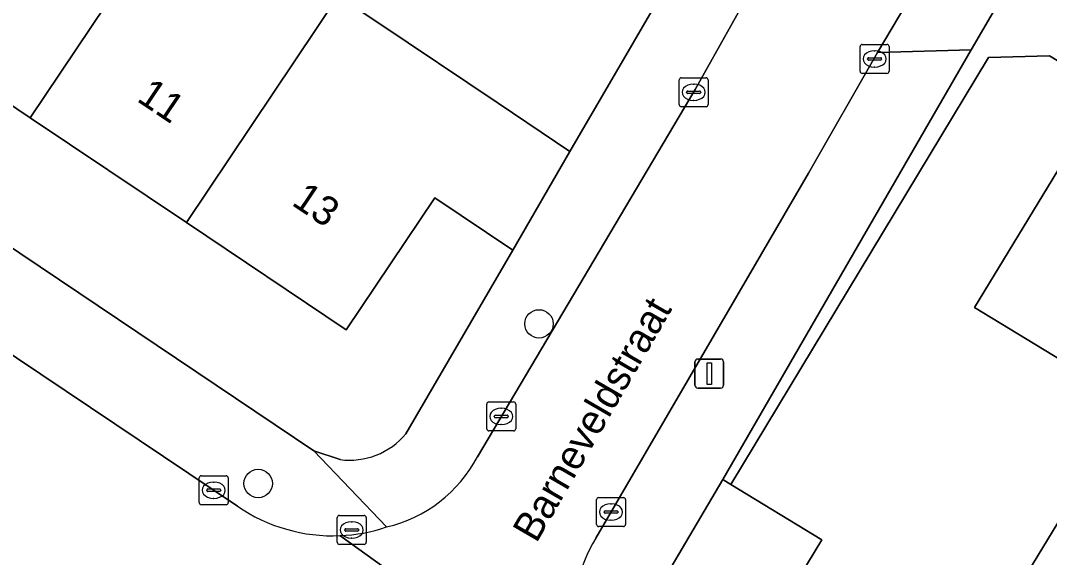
# Model space of a CAD drawing. Extents: x 158352 to 159489, y 383828 to 384603.
# Drawn here: x 158789.93 to 158825.42, y 383963.32 to 383981.83 of the extents above; entities that cross this region are included whole.
import ezdxf

# ---------------------------------------------------------------- set-up
doc = ezdxf.new("R2010")
doc.units = 0
for name, color, linetype in [('IMGEO_Boom', 7, 'Continuous'), ('IMGEO_Brandkraan', 7, 'Continuous'), ('IMGEO_Erf', 7, 'Continuous'), ('IMGEO_Kolk', 7, 'Continuous'), ('IMGEO_Lichtmast', 7, 'Continuous'), ('IMGEO_Openbare_ruimte_label', 7, 'Continuous'), ('IMGEO_Pand', 7, 'Continuous'), ('IMGEO_Pand_nummerreeks', 7, 'Continuous'), ('IMGEO_Rijbaan_lokaal_open', 7, 'Continuous'), ('IMGEO_Voetpad_open', 7, 'Continuous')]:
    doc.layers.add(name, color=color, linetype=linetype)

msp = doc.modelspace()

# ---------------------------------------------------------------- linework, layer by layer
at = {"layer": 'IMGEO_Boom'}
for centre in [(158807.812, 383971.377), (158798.125, 383965.871)]:
    msp.add_circle(centre, 0.489, dxfattribs=at)
at = {"layer": 'IMGEO_Brandkraan'}
for p, q in [((158800.851, 383963.843), (158800.851, 383964.695)), ((158800.926, 383964.769), (158801.778, 383964.769)), ((158801.339, 383964.549), (158801.364, 383964.549)), ((158801.852, 383964.695), (158801.852, 383963.843)), ((158801.11, 383964.263), (158801.11, 383964.275)), ((158801.548, 383964.226), (158801.15, 383964.226)), ((158801.153, 383964.312), (158801.551, 383964.312)), ((158801.594, 383964.275), (158801.594, 383964.263)), ((158801.362, 383963.989), (158801.337, 383963.989)), ((158801.778, 383963.769), (158800.926, 383963.769))]:
    msp.add_line(p, q, dxfattribs=at)
for points in [[(158800.851, 383963.843), (158800.851, 383964.695)], [(158800.926, 383964.769), (158801.778, 383964.769)], [(158801.852, 383964.695), (158801.852, 383963.843)], [(158801.778, 383963.769), (158800.926, 383963.769)]]:
    msp.add_lwpolyline(points, dxfattribs=at)
for centre, radius, start, end in [((158800.928, 383964.693), 0.0765, 91.552, 178.448), ((158800.928, 383964.693), 0.0765, 91.552, 178.448), ((158801.776, 383964.693), 0.0765, 1.552, 88.448), ((158801.776, 383964.693), 0.0765, 1.552, 88.448), ((158801.15, 383964.272), 0.0403, 85.8775, 175.7526), ((158801.147, 383964.262), 0.0366, 178.938, 274.7102), ((158801.551, 383964.269), 0.043, 264.8664, 352.4533), ((158801.555, 383964.274), 0.0386, 1.7309, 96.639), ((158800.928, 383963.845), 0.0765, 181.552, 268.448), ((158800.928, 383963.845), 0.0765, 181.552, 268.448), ((158801.776, 383963.845), 0.0765, 271.552, 358.448), ((158801.776, 383963.845), 0.0765, 271.552, 358.448)]:
    msp.add_arc(centre, radius, start, end, dxfattribs=at)
for centre, major_axis, ratio, start_param, end_param in [((158801.338, 383964.269), (-0.387, 0.002), 0.722429, 4.712389, 7.853982), ((158801.363, 383964.269), (-0.39, 0.002), 0.717154, 1.570796, 4.712389)]:
    msp.add_ellipse(centre, major_axis=major_axis, ratio=ratio, start_param=start_param, end_param=end_param, dxfattribs=at)
at = {"layer": 'IMGEO_Erf'}
for points in [[(158802.097, 384002.012), (158799.476, 383998.101), (158797.684, 383995.427), (158795.003, 383997.224), (158790.103, 383989.919), (158795.501, 383986.297), (158800.89, 383982.683), (158802.252, 383981.769), (158806.404, 383978.983), (158808.882, 383977.32), (158813.315, 383984.944), (158808.396, 383988.244), (158805.207, 383983.49), (158802.603, 383985.237), (158805.792, 383989.991), (158803.033, 383991.842), (158804.825, 383994.513), (158807.584, 383992.662), (158810.663, 383997.498), (158810.838, 383997.754), (158812.948, 383995.246), (158812.308, 383998.709), (158812.069, 384000)], [(158795.651, 383974.873), (158790.263, 383978.487), (158784.865, 383982.109), (158779.474, 383985.725), (158774.102, 383989.328), (158768.703, 383992.949), (158763.122, 383996.693), (158760.865, 383993.334), (158800.049, 383966.997), (158800.949, 383966.697)], [(158849.616, 383965.92), (158846.84, 383967.608), (158845.169, 383964.859), (158842.366, 383966.562), (158839.602, 383968.242), (158841.273, 383970.991), (158835.6, 383974.441), (158833.929, 383971.692), (158831.114, 383973.403), (158828.362, 383975.075), (158830.033, 383977.824), (158827.393, 383979.426), (158822.843, 383971.94), (158828.233, 383968.664), (158826.585, 383965.952), (158832.219, 383962.527), (158837.825, 383959.119), (158843.416, 383955.721), (158848.864, 383952.409)], [(158803.223, 383967.587), (158806.907, 383973.916), (158804.217, 383975.722), (158801.166, 383971.174), (158795.651, 383974.873)], [(158849.585, 383940.963), (158843.929, 383944.401), (158838.53, 383947.683), (158832.926, 383951.089), (158827.264, 383954.531), (158821.699, 383957.914), (158816.018, 383961.367), (158817.576, 383963.931), (158814.431, 383965.842), (158814.158, 383966.008), (158811.467, 383961.443)]]:
    msp.add_lwpolyline(points, dxfattribs=at)
msp.add_arc((158801.279, 383969.204), 2.529, 262.504, 320.2449, dxfattribs=at)
at = {"layer": 'IMGEO_Kolk'}
for p, q in [((158818.893, 383980.087), (158818.893, 383980.939)), ((158818.968, 383981.013), (158819.82, 383981.013)), ((158819.894, 383980.939), (158819.894, 383980.087)), ((158819.152, 383980.507), (158819.152, 383980.519)), ((158819.195, 383980.556), (158819.593, 383980.556)), ((158819.381, 383980.793), (158819.406, 383980.793)), ((158819.636, 383980.519), (158819.636, 383980.507)), ((158819.59, 383980.47), (158819.192, 383980.47)), ((158819.404, 383980.233), (158819.379, 383980.233)), ((158812.649, 383978.937), (158812.649, 383979.789)), ((158812.724, 383979.863), (158813.576, 383979.863)), ((158813.65, 383979.789), (158813.65, 383978.937)), ((158819.82, 383980.013), (158818.968, 383980.013)), ((158813.137, 383979.643), (158813.162, 383979.643)), ((158812.908, 383979.357), (158812.908, 383979.369)), ((158813.346, 383979.32), (158812.948, 383979.32)), ((158812.951, 383979.406), (158813.349, 383979.406)), ((158813.16, 383979.083), (158813.135, 383979.083)), ((158813.392, 383979.369), (158813.392, 383979.357)), ((158813.576, 383978.863), (158812.724, 383978.863)), ((158806.012, 383967.758), (158806.012, 383968.61)), ((158806.087, 383968.684), (158806.939, 383968.684)), ((158806.5, 383968.464), (158806.525, 383968.464)), ((158807.013, 383968.61), (158807.013, 383967.758)), ((158806.271, 383968.178), (158806.271, 383968.19)), ((158806.709, 383968.141), (158806.311, 383968.141)), ((158806.314, 383968.227), (158806.712, 383968.227)), ((158806.755, 383968.19), (158806.755, 383968.178)), ((158806.523, 383967.904), (158806.498, 383967.904)), ((158806.939, 383967.684), (158806.087, 383967.684)), ((158796.09, 383965.213), (158796.09, 383966.065)), ((158796.165, 383966.139), (158797.017, 383966.139)), ((158797.091, 383966.065), (158797.091, 383965.213)), ((158796.349, 383965.633), (158796.349, 383965.645)), ((158796.787, 383965.596), (158796.389, 383965.596)), ((158796.392, 383965.682), (158796.79, 383965.682)), ((158796.578, 383965.919), (158796.603, 383965.919)), ((158796.833, 383965.645), (158796.833, 383965.633)), ((158796.601, 383965.359), (158796.576, 383965.359)), ((158809.798, 383964.462), (158809.798, 383965.314)), ((158809.873, 383965.388), (158810.725, 383965.388)), ((158810.799, 383965.314), (158810.799, 383964.462)), ((158797.017, 383965.139), (158796.165, 383965.139)), ((158810.057, 383964.882), (158810.057, 383964.894)), ((158810.1, 383964.931), (158810.498, 383964.931)), ((158810.286, 383965.168), (158810.311, 383965.168)), ((158810.541, 383964.894), (158810.541, 383964.882)), ((158810.495, 383964.845), (158810.097, 383964.845)), ((158810.309, 383964.608), (158810.284, 383964.608)), ((158810.725, 383964.388), (158809.873, 383964.388))]:
    msp.add_line(p, q, dxfattribs=at)
for points in [[(158818.893, 383980.087), (158818.893, 383980.939)], [(158818.968, 383981.013), (158819.82, 383981.013)], [(158819.894, 383980.939), (158819.894, 383980.087)], [(158812.649, 383978.937), (158812.649, 383979.789)], [(158812.724, 383979.863), (158813.576, 383979.863)], [(158813.65, 383979.789), (158813.65, 383978.937)], [(158819.82, 383980.013), (158818.968, 383980.013)], [(158813.576, 383978.863), (158812.724, 383978.863)], [(158806.012, 383967.758), (158806.012, 383968.61)], [(158806.087, 383968.684), (158806.939, 383968.684)], [(158807.013, 383968.61), (158807.013, 383967.758)], [(158806.939, 383967.684), (158806.087, 383967.684)], [(158796.09, 383965.213), (158796.09, 383966.065)], [(158796.165, 383966.139), (158797.017, 383966.139)], [(158797.091, 383966.065), (158797.091, 383965.213)], [(158809.798, 383964.462), (158809.798, 383965.314)], [(158809.873, 383965.388), (158810.725, 383965.388)], [(158810.799, 383965.314), (158810.799, 383964.462)], [(158797.017, 383965.139), (158796.165, 383965.139)], [(158810.725, 383964.388), (158809.873, 383964.388)]]:
    msp.add_lwpolyline(points, dxfattribs=at)
for centre, radius, start, end in [((158818.97, 383980.937), 0.0765, 91.552, 178.448), ((158818.97, 383980.937), 0.0765, 91.552, 178.448), ((158819.818, 383980.937), 0.0765, 1.552, 88.448), ((158819.818, 383980.937), 0.0765, 1.552, 88.448), ((158819.192, 383980.516), 0.0403, 85.8775, 175.7526), ((158819.189, 383980.506), 0.0366, 178.938, 274.7102), ((158819.593, 383980.513), 0.043, 264.8664, 352.4533), ((158819.597, 383980.518), 0.0386, 1.7309, 96.639), ((158812.726, 383979.787), 0.0765, 91.552, 178.448), ((158812.726, 383979.787), 0.0765, 91.552, 178.448), ((158813.574, 383979.787), 0.0765, 1.552, 88.448), ((158813.574, 383979.787), 0.0765, 1.552, 88.448), ((158818.97, 383980.089), 0.0765, 181.552, 268.448), ((158818.97, 383980.089), 0.0765, 181.552, 268.448), ((158819.818, 383980.089), 0.0765, 271.552, 358.448), ((158819.818, 383980.089), 0.0765, 271.552, 358.448), ((158812.948, 383979.366), 0.0403, 85.8775, 175.7526), ((158812.945, 383979.356), 0.0366, 178.938, 274.7102), ((158813.349, 383979.363), 0.043, 264.8664, 352.4533), ((158813.353, 383979.368), 0.0386, 1.7309, 96.639), ((158812.726, 383978.939), 0.0765, 181.552, 268.448), ((158812.726, 383978.939), 0.0765, 181.552, 268.448), ((158813.574, 383978.939), 0.0765, 271.552, 358.448), ((158813.574, 383978.939), 0.0765, 271.552, 358.448), ((158806.089, 383968.608), 0.0765, 91.552, 178.448), ((158806.089, 383968.608), 0.0765, 91.552, 178.448), ((158806.937, 383968.608), 0.0765, 1.552, 88.448), ((158806.937, 383968.608), 0.0765, 1.552, 88.448), ((158806.311, 383968.187), 0.0403, 85.8775, 175.7526), ((158806.308, 383968.177), 0.0366, 178.938, 274.7102), ((158806.712, 383968.184), 0.043, 264.8664, 352.4533), ((158806.716, 383968.189), 0.0386, 1.7309, 96.639), ((158806.089, 383967.76), 0.0765, 181.552, 268.448), ((158806.089, 383967.76), 0.0765, 181.552, 268.448), ((158806.937, 383967.76), 0.0765, 271.552, 358.448), ((158806.937, 383967.76), 0.0765, 271.552, 358.448), ((158796.167, 383966.063), 0.0765, 91.552, 178.448), ((158796.167, 383966.063), 0.0765, 91.552, 178.448), ((158797.015, 383966.063), 0.0765, 1.552, 88.448), ((158797.015, 383966.063), 0.0765, 1.552, 88.448), ((158796.389, 383965.642), 0.0403, 85.8775, 175.7526), ((158796.386, 383965.632), 0.0366, 178.938, 274.7102), ((158796.79, 383965.639), 0.043, 264.8664, 352.4533), ((158796.794, 383965.644), 0.0386, 1.7309, 96.639), ((158809.875, 383965.312), 0.0765, 91.552, 178.448), ((158809.875, 383965.312), 0.0765, 91.552, 178.448), ((158810.723, 383965.312), 0.0765, 1.552, 88.448), ((158810.723, 383965.312), 0.0765, 1.552, 88.448), ((158796.167, 383965.215), 0.0765, 181.552, 268.448), ((158796.167, 383965.215), 0.0765, 181.552, 268.448), ((158797.015, 383965.215), 0.0765, 271.552, 358.448), ((158797.015, 383965.215), 0.0765, 271.552, 358.448), ((158810.097, 383964.891), 0.0403, 85.8775, 175.7526), ((158810.094, 383964.881), 0.0366, 178.938, 274.7102), ((158810.498, 383964.888), 0.043, 264.8664, 352.4533), ((158810.502, 383964.893), 0.0386, 1.7309, 96.639), ((158809.875, 383964.464), 0.0765, 181.552, 268.448), ((158809.875, 383964.464), 0.0765, 181.552, 268.448), ((158810.723, 383964.464), 0.0765, 271.552, 358.448), ((158810.723, 383964.464), 0.0765, 271.552, 358.448)]:
    msp.add_arc(centre, radius, start, end, dxfattribs=at)
for centre, major_axis, ratio, start_param, end_param in [((158819.38, 383980.513), (-0.387, 0.002), 0.722429, 4.712389, 7.853982), ((158819.405, 383980.513), (-0.39, 0.002), 0.717154, 1.570796, 4.712389), ((158813.136, 383979.363), (-0.387, 0.002), 0.722429, 4.712389, 7.853982), ((158813.161, 383979.363), (-0.39, 0.002), 0.717154, 1.570796, 4.712389), ((158806.499, 383968.184), (-0.387, 0.002), 0.722429, 4.712389, 7.853982), ((158806.524, 383968.184), (-0.39, 0.002), 0.717154, 1.570796, 4.712389), ((158796.577, 383965.639), (-0.387, 0.002), 0.722429, 4.712389, 7.853982), ((158796.602, 383965.639), (-0.39, 0.002), 0.717154, 1.570796, 4.712389), ((158810.285, 383964.888), (-0.387, 0.002), 0.722429, 4.712389, 7.853982), ((158810.31, 383964.888), (-0.39, 0.002), 0.717154, 1.570796, 4.712389)]:
    msp.add_ellipse(centre, major_axis=major_axis, ratio=ratio, start_param=start_param, end_param=end_param, dxfattribs=at)
at = {"layer": 'IMGEO_Lichtmast'}
for p, q in [((158813.191, 383969.262), (158813.191, 383970.062)), ((158813.191, 383970.062), (158813.191, 383969.262)), ((158813.291, 383970.162), (158814.081, 383970.162)), ((158814.081, 383970.162), (158813.291, 383970.162)), ((158814.181, 383970.062), (158814.181, 383969.262)), ((158814.181, 383969.262), (158814.181, 383970.062)), ((158814.081, 383969.162), (158813.291, 383969.162)), ((158813.291, 383969.162), (158814.081, 383969.162))]:
    msp.add_line(p, q, dxfattribs=at)
msp.add_lwpolyline([(158813.611, 383970.037), (158813.761, 383970.037), (158813.761, 383969.287), (158813.611, 383969.287), (158813.611, 383970.037)], dxfattribs=at)
for centre, start, end in [((158813.291, 383970.062), 90, 180), ((158813.291, 383970.062), 90, 180), ((158814.081, 383970.062), 0, 90), ((158814.081, 383970.062), 360, 90), ((158813.291, 383969.262), 180, 270), ((158813.291, 383969.262), 180, 270), ((158814.081, 383969.262), 270, 0), ((158814.081, 383969.262), 270, 0)]:
    msp.add_arc(centre, 0.1, start, end, dxfattribs=at)
at = {"layer": 'IMGEO_Pand'}
for points in [[(158790.263, 383978.487), (158795.501, 383986.297), (158790.103, 383989.919), (158784.865, 383982.109)], [(158790.263, 383978.487), (158795.651, 383974.873), (158800.89, 383982.683), (158795.501, 383986.297)], [(158808.882, 383977.32), (158806.404, 383978.983), (158802.252, 383981.769), (158800.89, 383982.683), (158795.651, 383974.873), (158801.166, 383971.174), (158804.217, 383975.722), (158806.907, 383973.916)], [(158827.393, 383979.426), (158825.424, 383980.625), (158823.318, 383980.566), (158814.431, 383965.842), (158817.576, 383963.931), (158816.018, 383961.367), (158821.699, 383957.914), (158826.585, 383965.952), (158828.233, 383968.664), (158822.843, 383971.94)], [(158827.264, 383954.531), (158832.219, 383962.527), (158826.585, 383965.952), (158821.699, 383957.914)]]:
    msp.add_lwpolyline(points, close=True, dxfattribs=at)
at = {"layer": 'IMGEO_Rijbaan_lokaal_open'}
for points in [[(158851.565, 383989.958), (158839.385, 383987.718), (158836.159, 383987.092), (158833.861, 383986.646), (158828.945, 383985.73), (158825.129, 383984.951), (158824.65, 383984.127), (158822.729, 383980.822), (158814.158, 383966.008), (158814.431, 383965.842), (158823.318, 383980.566), (158825.424, 383980.625), (158827.393, 383979.426), (158830.033, 383977.824), (158832.785, 383976.152), (158835.6, 383974.441), (158841.273, 383970.991), (158844.042, 383969.309), (158846.84, 383967.608), (158849.616, 383965.92)], [(158817.116, 383976.574), (158819.496, 383980.731), (158820.72, 383982.81)], [(158814.906, 383982.489), (158813.204, 383979.453), (158805.689, 383966.794)], [(158797.412, 383965.088), (158772.851, 383981.561), (158767.881, 383974.094), (158772.196, 383971.212), (158807.716, 383947.485), (158815.119, 383942.928), (158821.005, 383939.346), (158825.751, 383947.179), (158811.929, 383955.585)], [(158809.769, 383963.981), (158817.116, 383976.574)], [(158800.948, 383964.073), (158809.759, 383957.733)], [(158809.759, 383957.733), (158800.948, 383964.073)]]:
    msp.add_lwpolyline(points, dxfattribs=at)
for centre, radius, start, end in [((158801.457, 383969.031), 4.786, 283.2699, 332.1425), ((158800.698, 383969.871), 5.803, 235.5037, 272.4643), ((158800.73, 383969.716), 5.647, 272.2073, 288.8598), ((158815.385, 383960.685), 6.512, 149.586, 180.2597)]:
    msp.add_arc(centre, radius, start, end, dxfattribs=at)
at = {"layer": 'IMGEO_Voetpad_open'}
for points in [[(158688.754, 384037.85), (158713.384, 384021.411), (158715.596, 384019.935), (158744.584, 384000.725), (158747.04, 383999.013), (158767.638, 383985.057), (158770.642, 383983.042), (158772.851, 383981.561), (158797.412, 383965.088)], [(158802.556, 383964.372), (158800.049, 383966.997), (158760.865, 383993.334), (158759.062, 383994.546), (158750.948, 384000), (158706.944, 384029.577)], [(158820.72, 383982.81), (158819.496, 383980.731), (158822.729, 383980.822), (158824.65, 383984.127), (158821.588, 383986.196)], [(158813.961, 383986.055), (158813.315, 383984.944), (158808.882, 383977.32), (158806.907, 383973.916), (158803.223, 383967.587)], [(158813.204, 383979.453), (158814.906, 383982.489)], [(158822.729, 383980.822), (158819.496, 383980.731), (158817.116, 383976.574), (158809.769, 383963.981)], [(158811.467, 383961.443), (158814.158, 383966.008), (158822.729, 383980.822)], [(158805.689, 383966.794), (158813.204, 383979.453)], [(158800.949, 383966.697), (158800.049, 383966.997), (158802.556, 383964.372)]]:
    msp.add_lwpolyline(points, dxfattribs=at)
for centre, radius, start, end in [((158801.279, 383969.204), 2.529, 262.504, 320.2449), ((158801.457, 383969.031), 4.786, 283.2699, 332.1425), ((158800.698, 383969.871), 5.803, 235.5037, 272.4643), ((158800.73, 383969.716), 5.647, 272.2073, 288.8598), ((158815.385, 383960.685), 6.512, 149.586, 180.2597)]:
    msp.add_arc(centre, radius, start, end, dxfattribs=at)

# ---------------------------------------------------------------- texts
at = {"layer": 'IMGEO_Openbare_ruimte_label'}
msp.add_text('Barneveldstraat', height=1, rotation=59.921, dxfattribs=at).set_placement((158807.723, 383963.788))
at = {"layer": 'IMGEO_Pand_nummerreeks'}
for s, rotation, p in [('11', 326.1472, (158793.901, 383979.081)), ('13', 326.1497, (158799.242, 383975.499))]:
    msp.add_text(s, height=1, rotation=rotation, dxfattribs=at).set_placement(p)

doc.saveas('drawing.dxf')
